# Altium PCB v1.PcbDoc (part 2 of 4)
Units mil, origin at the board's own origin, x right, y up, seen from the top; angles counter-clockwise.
Board outline 4875 x 2022 mil, 4 copper layers (Top Layer, Signal Layer 1, Signal Layer 2, Bottom Layer), stack 64.834 mil thick; 432 components, 288 nets, 1177 pads, 637 vias.
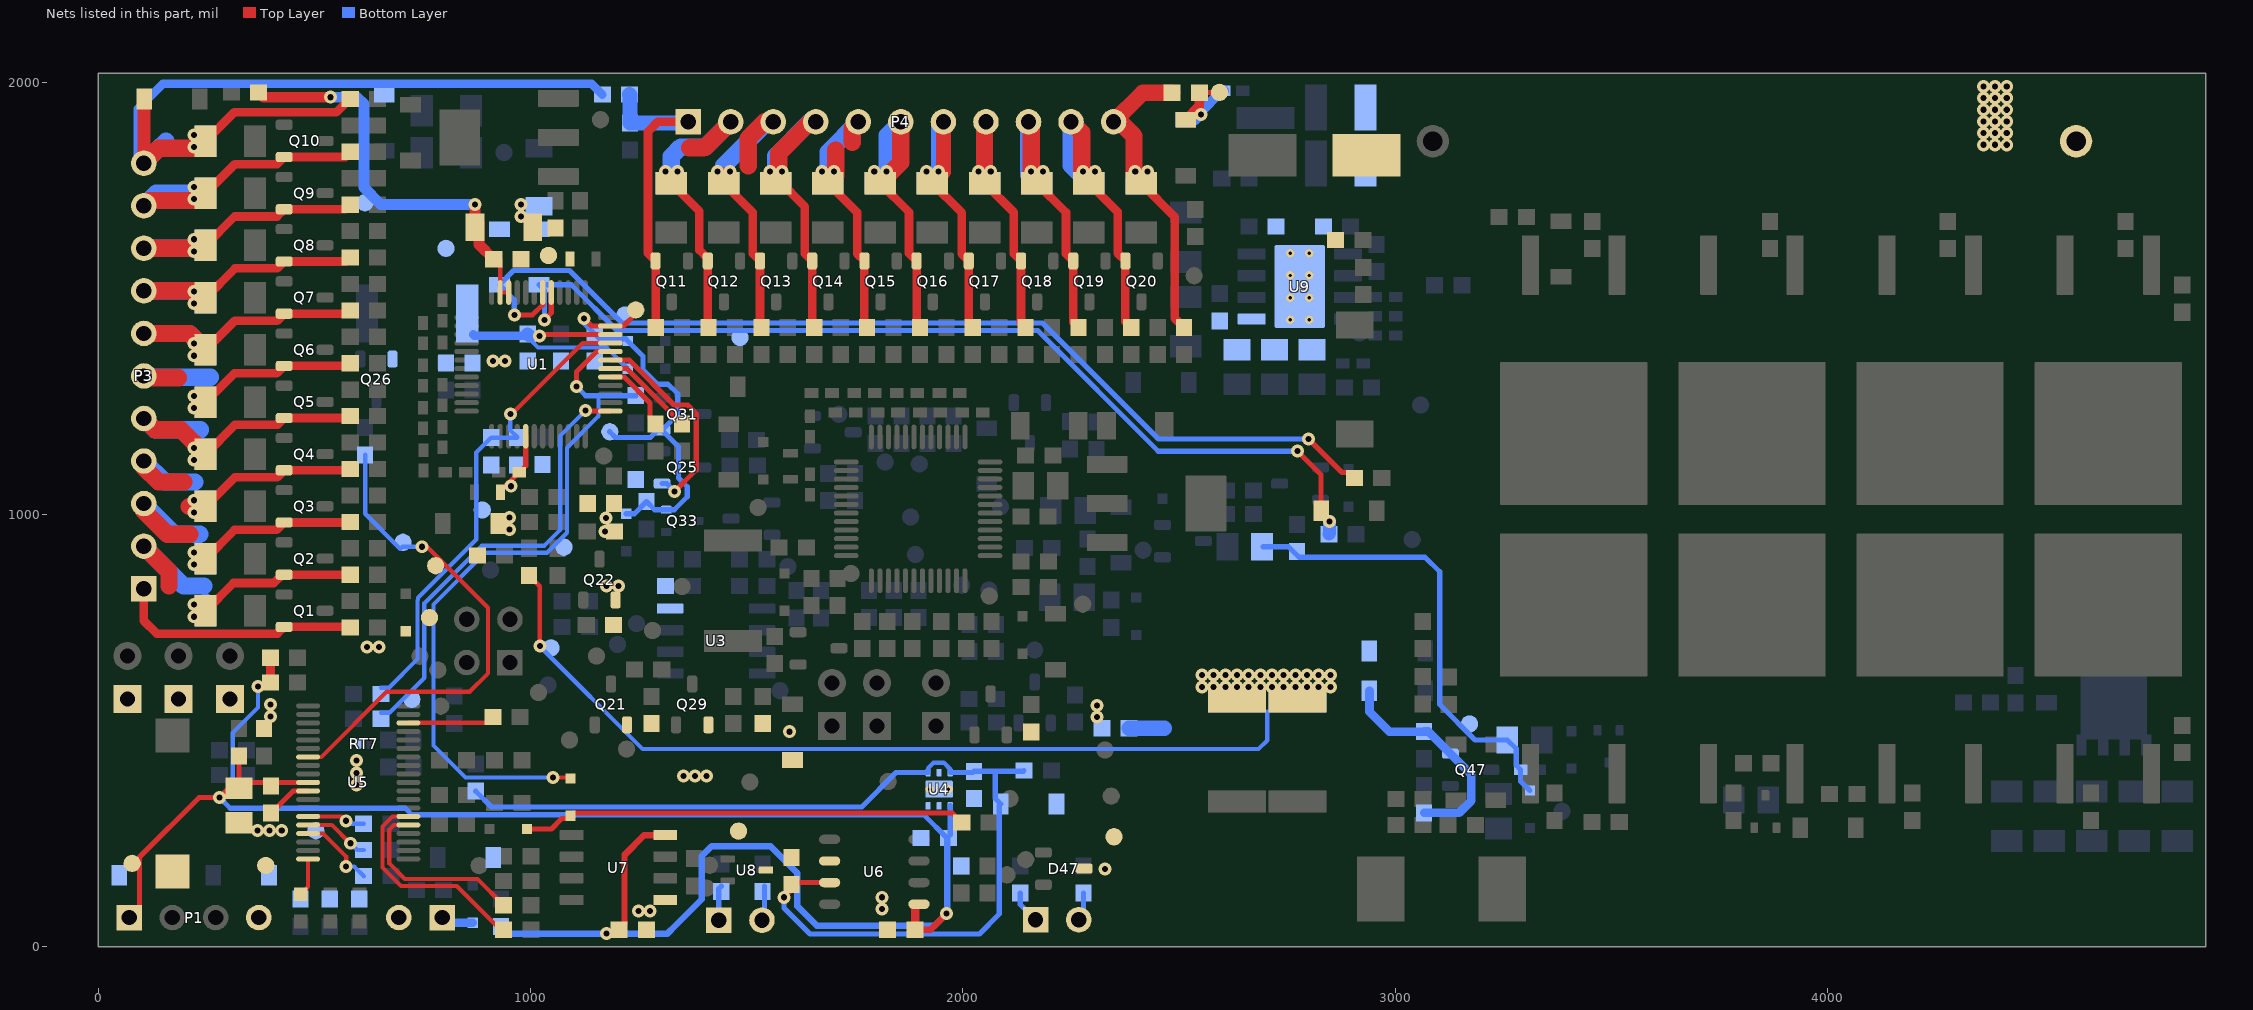
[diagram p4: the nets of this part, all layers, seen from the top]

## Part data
C1 C2 C3 C4 C5 C6 C7 C8 C9 C10 C12 C13 C14 C15 C16 C17 C18 C19 C20 C21: "CAP, CERM, 0.1 µF, 25 V,+/- 10%, X7R, 0402", Cap_Case=0402, Manufacturer=MuRata, Supplier Part Number 1=490-10698-1-ND, TempCo=X7R, Tolerance_%=10, Value2=25V, ValueDisplayed=0.1µF
C11 C22 C36 C37 C42 C43 C46 C64 C66 C68 C69 C70: "CAP, CERM, 0.1 µF, 50 V,+/- 10%, X7R, 0603", Cap_Case=0603, Manufacturer=MuRata, Supplier Part Number 1=490-1519-1-ND, TempCo=X7R, Tolerance_%=10, Value2=50V, ValueDisplayed=0.1µF
C23 C24: library part GRM31CR72A225KA73L, "CAP, CERM, 2.2 µF, 100 V,+/- 10%, X7R, 1206", Cap_Case=1206, Manufacturer="Holy Stone Enterprise", Supplier Part Number 1=490-7209-1-ND, TempCo=X7R, Tolerance_%=10, Value2=100V, ValueDisplayed=2.2µF
C25 C26 C27 C28 C38 C39 C50 C59 C77: "CAP, CERM, 100 pF, 100 V,+/- 5%, C0G/NP0, 0603", Cap_Case=0603, Manufacturer=MuRata, Supplier Part Number 1=490-1351-1-ND, TempCo=C0G/NP0, Tolerance_%=5, Value2=100V, ValueDisplayed=100pF
C29: "CAP, CERM, 2.2 µF, 25 V,+/- 10%, X7R, 0805", Cap_Case=0805, Manufacturer=MuRata, Supplier Part Number 1=490-3331-1-ND, TempCo=X7R, Tolerance_%=10, Value1="0.005 ohm", Value2=25V, ValueDisplayed=2.2µF
C30 C31 C65: "CAP, CERM, 2.2 µF, 16 V,+/- 10%, X7R, 0603", Cap_Case=0603, Manufacturer="Taiyo Yuden", Supplier Part Number 1=587-4864-1-ND, TempCo=X7R, Tolerance_%=10, Value2=16V, ValueDisplayed=2.2µF
C32 C33 C34 C35 C62: "CAP, CERM, 1 µF, 16 V,+/- 10%, X7R, AEC-Q200 Grade 1, 0603", Cap_Case=0603, Manufacturer=MuRata, Supplier Part Number 1=490-5241-6-ND, TempCo=X7R, Tolerance_%=10, Value2=16V, ValueDisplayed=1µF
C40 C41: "CAP, CERM, 0.022 µF, 50 V,+/- 10%, X7R, 0603", Cap_Case=0603, Manufacturer=MuRata, Supplier Part Number 1=490-1517-1-ND, TempCo=X7R, Tolerance_%=10, Value2=50V, ValueDisplayed=0.022µF
C44 C45: "CAP, CERM, 1 µF, 100 V,+/- 10%, X7R, 1206", Cap_Case=1206, Manufacturer=TDK, Supplier Part Number 1=445-4467-1-ND, TempCo=X7R, Tolerance_%=10, Value1="0.004575 ohm", Value2=100V, ValueDisplayed=1µF
C47 C53 C56: "CAP, CERM, 47 pF, 50 V,+/- 5%, C0G/NP0, 0603", Cap_Case=0603, Manufacturer=MuRata, Supplier Part Number 1=490-1419-1-ND, TempCo=C0G/NP0, Tolerance_%=5, Value2=50V, ValueDisplayed=47pF
C48 C49 C51 C52 C54 C55: "CAP, CERM, 470 pF, 50 V,+/- 10%, X7R, 0603", Cap_Case=0603, Manufacturer=MuRata, Supplier Part Number 1=490-1489-1-ND, TempCo=X7R, Tolerance_%=10, Value2=50V, ValueDisplayed=470pF
C57 C58 C60 C61 C73: "CAP, CERM, 0.1 µF, 100 V,+/- 10%, X7R, 0603", Cap_Case=0603, Manufacturer=MuRata, Supplier Part Number 1=490-3285-1-ND, TempCo=X7R, Tolerance_%=10, Value2=100V, ValueDisplayed=0.1µF
C63: "CAP, CERM, 10 µF, 16 V,+/- 10%, X6S, 0805", Cap_Case=0805, Manufacturer=TDK, Supplier Part Number 1=445-14483-1-ND, TempCo=X6S, Tolerance_%=10, Value1="0.002818 ohm", Value2=16V, ValueDisplayed=10µF
C67: "CAP, CERM, 1000 pF, 50 V,+/- 5%, C0G/NP0, 0603", Cap_Case=0603, Manufacturer=MuRata, Supplier Part Number 1=490-1451-1-ND, TempCo=C0G/NP0, Tolerance_%=5, Value2=50V, ValueDisplayed=1000pF
C71 C72: "CAP, CERM, 4.7 µF, 100 V,+/- 10%, X7S, 1210", Cap_Case=1210, Manufacturer=TDK, Supplier Part Number 1=445-8912-1-ND, TempCo=X7S, Tolerance_%=10, Value2=100V, ValueDisplayed=4.7µF
C74: library part UUX2A4R7MCL1GS, "CAP, AL, 10 µF, 100 V, +/- 20%, SMD", Cap_Case=8x6.2mm, Manufacturer=Nichicon, Supplier Part Number 1=493-6282-1-ND, Tolerance_%=20, Value2=100V, ValueDisplayed=10µF
C75: "CAP, CERM, 56 pF, 50 V,+/- 5%, C0G/NP0, 0603", Cap_Case=0603, Manufacturer=MuRata, Supplier Part Number 1=490-1421-1-ND, TempCo=C0G/NP0, Tolerance_%=5, Value2=50V, ValueDisplayed=NC
C76: "CAP, CERM, 2200 pF, 50 V,+/- 10%, X7R, 0402", Cap_Case=0402, Manufacturer=MuRata, Supplier Part Number 1=490-1305-1-ND, TempCo=X7R, Tolerance_%=10, Value2=50V, ValueDisplayed=2200pF
C78: "CAP, CERM, 1500 pF, 50 V,+/- 10%, X7R, 0402", Cap_Case=0402, Manufacturer=MuRata, Supplier Part Number 1=490-3245-1-ND, TempCo=X7R, Tolerance_%=10, Value2=50V, ValueDisplayed=1500pF
C79 C80 C81: "CAP, CERM, 4.7 µF, 16 V,+/- 10%, X7R, 0805", Cap_Case=0805, Manufacturer=MuRata, Supplier Part Number 1=490-4522-1-ND, TempCo=X7R, Tolerance_%=10, Value1="0.006 ohm", Value2=16V, ValueDisplayed=4.7µF
D1 D4 D6 D8 D9 D11 D12 D32 D33 D35 D36: "Diode, Schottky, 100 V, 0.15 A, SOD-123", Manufacturer="Diodes Inc.", Supplier Part Number 1=BAT46W-7FDICT-ND, Value1=0.15A, Value2=0.6V
D2 D5 D10: "Diode, Schottky, 30 V, 0.2 A, SOD-323", Manufacturer="Diodes Inc.", Supplier Part Number 1=BAT42WSDICT-ND, Value1=0.2A, Value2=1V
D3 D7 D15 D39 D40 D41: "Diode, Zener, 3.6 V, 500 mW, SOD-123", Manufacturer="ON Semiconductor", Power_W=0.5, Supplier Part Number 1=MMSZ4685T1GOSCT-ND, Value1=0.5W
D13 D14 D46 D49: "Diode, Schottky, 20 V, 0.5 A, SOD-323F", Manufacturer=Panasonic, Supplier Part Number 1=DB2J20900LCT-ND, Value1=0.5A, Value2=0.5V
D16: library part BAT42WS-7-F, "Diode, Schottky, 30 V, 0.2 A, SOD-323", Manufacturer="Diodes Inc.", Supplier Part Number 1=BAT42WSDICT-ND, Value1=0.2A, Value2=1V
D17 D19 D21 D31 D34: "Diode, Zener, 16 V, 500 mW, SOD-123", Manufacturer="Diodes Inc.", Power_W=0.5, Supplier Part Number 1=MMSZ5246B-FDICT-ND, Value1=0.5W
D18 D20 D26 D27: library part MMSZ5263BT1G, "Diode, Zener, 75V, 500 mW, AEC-Q101, SOD-123", Manufacturer="ON Semiconductor", Power_W=0.5, Supplier Part Number 1=MMSZ5263BT1GOSCT-ND, Value1=0.5W
D22: library part BAT46WJ,115, "Diode, Schottky, 100 V, 0.25 A, SOD-323F", Manufacturer=Nexperia, Supplier Part Number 1=568-6017-1-ND, Value1=0.25A, Value2=0.85V
D23 D24 D25 D28 D38: "Diode, Schottky, 100 V, 0.25 A, SOD-323F", Manufacturer=Nexperia, Supplier Part Number 1=568-6017-1-ND, Value1=0.25A, Value2=0.85V
D29 D48: "Diode, Switching, 100 V, 0.25 A, SOD-523", Manufacturer=Nexperia, Supplier Part Number 1=568-1603-1-ND, Value1=0.25A, Value2=1.25V
D30: "Diode, Zener, 5.1 V, 200 mW, SOD-323", Manufacturer="Diodes Inc.", Power_W=0.2, Supplier Part Number 1=BZT52C5V1S-FDICT-ND, Value1=0.2W
D37: "Diode, Ultrafast, 200 V, 3 A, SMC", Manufacturer=Vishay-Semiconductor, Supplier Part Number 1=ES3D-E3/57TGICT-ND, Value1=3A, Value2=0.9V
D42 D43 D44: "LED, Red, SMD", Color=Red, Manufacturer="Wurth Elektronik", Power_TotalModule=0.072, Supplier Part Number 1=732-4978-1-ND, Value1=0.072W, Value2=2V
D45: "Diode, Zener, 5.6 V, 500 mW, SOD-123", Manufacturer="ON Semiconductor", Power_W=0.5, Supplier Part Number 1=MMSZ4690T1GOSCT-ND, Value1=0.5W
D47: library part NUP2105LT1G, "Diode, TVS, Bi, 24 V, SOT-23", Manufacturer="ON Semiconductor", Power_W=0.35, Supplier Part Number 1=NUP2105LT1GOSCT-ND, Value1=0.35W
F1: library part 0325030, "Fuse, 30 A, 250 VAC, 125 VDC, TH", Alternate Manufacturer=-, Manufacturer=LittleFuse
L1 L2 L3 L4: "Ferrite Bead, 600 ohm @ 100 MHz, 0.2 A, 0603", Manufacturer="Wurth Elektronik", Supplier Part Number 1=732-1583-1-ND, Value1="0.45 ohm", Value2=0.2A, ValueDisplayed="600 ohm"
L5: "Inductor, Shielded, 1 µH, 2.7 A, 0.039 ohm, SMD", Manufacturer="Wurth Elektronik", Supplier Part Number 1=732-4863-1-ND, Value1="0.039 ohm", Value2=2.7A, ValueDisplayed=10µH
L6: "Inductor, Shielded Drum Core, Metal Composite, 68 µH, 0.87 A, 0.239 ohm, SMD", Manufacturer="Wurth Elektronik", Supplier Part Number 1=732-1201-1-ND, Value1="0.239 ohm", Value2=0.87A, ValueDisplayed=68µH
P1: "Header, 4-Pin"
P2: "Header, 2-Pin, Dual row"
P3 P4: "Header, 11-Pin"
P5 P6 P7: "Header, 2-Pin"
Q1 Q2 Q3 Q4 Q5 Q6 Q7 Q8 Q9 Q10 Q11 Q12 Q13 Q14 Q15 Q16 Q17 Q18 Q19 Q20: library part "BSR14, Nexperia", "Transistor, NPN, 40 V, 0.8 A, SOT-23", Manufacturer=Nexperia, Supplier Part Number 1=568-6225-1-ND, Value1="0.8 A", Value2=300
Q21: library part "BC846B,215, Nexperia", "Transistor, NPN, 65 V, 0.1 A, SOT-23", Manufacturer=Nexperia, Supplier Part Number 1=568-1632-1-ND, Value1="0.1 A", Value2=450
Q22 Q25 Q26 Q29 Q31 Q32: library part "MMBTA05LT1G, ON Semiconductor", "Transistor, NPN, 60 V, 0.5 A, AEC-Q101, SOT-23", Manufacturer="ON Semiconductor", Supplier Part Number 1=MMBTA05LT1GOSCT-ND, Value1="0.5 A"
Q23 Q24: library part "FZT493TA, Diodes Inc.", "Transistor, NPN, 60 V, 1 A, SOT-223", Manufacturer="Diodes Inc.", Supplier Part Number 1=FZT493CT-ND, Value1="1 A", Value2=300
Q27 Q28 Q30 Q34 Q35: library part "MMBTA56LT1G, ON Semiconductor", "Transistor, PNP, 80 V, 0.5 A, SOT-23", Manufacturer="ON Semiconductor", Supplier Part Number 1=MMBTA56LT1GOSDKR-ND, Value1="0.5 A"
Q33 Q49: "MOSFET, P-CH, -20 V, -0.82 A, SOT-323", Alternate Manufacturer=None, Manufacturer="Diodes Inc.", Supplier Part Number 1=DMG1013UW-7DICT-ND, Value1="0.75 ohm", Value2="0.622 nC"
Q36 Q37 Q38 Q39 Q42 Q43 Q44 Q45: "MOSFET, N-CH, 100 V, 200 A, KTT0002A (TO-263-2)", Alternate Manufacturer=None, Manufacturer="Texas Instruments", Supplier Part Number 1=296-41136-1-ND, Value1="? ohm", Value2="118 nC"
Q40: "MOSFET, P-CH, -150 V, -3 A, PowerPAK SO-8", Alternate Manufacturer=None, Manufacturer=Vishay-Siliconix, Supplier Part Number 1=SI7439DP-T1-E3CT-ND, Value1="? ohm", Value2="88 nC"
Q41: "MOSFET, P-CH, -150 V, -0.53 A, SOT-23", Alternate Manufacturer=None, Manufacturer=Vishay-Siliconix, Supplier Part Number 1=SI2325DS-T1-E3CT-ND, Value1="? ohm", Value2="7.7 nC"
Q46: library part "FMMT495TA, Diodes Inc.", "Transistor, NPN, 150 V, 1 A, AEC-Q101, SOT-23", Manufacturer="Diodes Inc.", Supplier Part Number 1=FMMT495CT-ND, Value1="1 A", Value2=300
Q47: library part BSS123, "MOSFET, N-CH, 250V, 0.35 A, SOT-23", Alternate Manufacturer=None, Manufacturer="Fairchild Semiconductor", Supplier Part Number 1=BSS123NCT-ND, Value1="10 ohm", Value2="1.8 nC"
Q48: "MOSFET, N-CH, 60 V, 0.115 A, SOT-323", Alternate Manufacturer=None, Manufacturer="Diodes Inc.", Supplier Part Number 1=2N7002W-FDICT-ND, Value1="7.5 ohm", Value2="? nC"
R1 R3 R5 R7 R9 R11 R13 R15 R17 R19 R43 R44 R46 R48 R50 R52 R54 R56 R58 R60: "RES, 80.6, 1%, 0.25 W, 1206", Manufacturer=Vishay-Dale, Power_W=0.25, Supplier Part Number 1=541-80.6FCT-ND, TempCo="100 ppm/C", Tolerance_%=1, Value1=1%, Value2=0.25W, Value_Code=80R6
R2 R4 R6 R8 R10 R12 R14 R16 R18 R20 R42 R45 R47 R49 R51 R53 R55 R57 R59 R61: "RES, 80.6, 1%, 0.25 W, 1206", Manufacturer=Vishay-Dale, Power_W=0.25, Supplier Part Number 1=541-80.6FCT-ND, TempCo="100 ppm/C", Tolerance_%=1, Value1=1%, Value2=0.25W, Value_Code=80R6, ValueDisplayed=80.6
R21 R23 R25 R27 R29 R31 R33 R35 R37 R39 R64 R66 R68 R70 R72 R74 R76 R78 R80 R82 R88 R90 R97 R98 R102 R103 R105 R106 R180 R181 R182 R183 R184 R185 R186 R187 R188 R192 R193 R194 R195 R196 R197 R201 R202 R209: "RES, 100, 1%, 0.1 W, 0603", Manufacturer=Vishay-Dale, Power_W=0.1, Supplier Part Number 1=541-100HCT-ND, TempCo="100 ppm/C", Tolerance_%=1, Value1=1%, Value2=0.1W, Value_Code=100R, ValueDisplayed=100
R22 R24 R26 R28 R30 R32 R34 R36 R38 R40 R65 R67 R69 R71 R73 R75 R77 R79 R81 R83: "RES, 300, 5%, 0.1 W, 0603", Manufacturer=Vishay-Dale, Power_W=0.1, Supplier Part Number 1=541-300GCT-ND, TempCo="200 ppm/C", Tolerance_%=5, Value1=5%, Value2=0.1W, Value_Code=300R, ValueDisplayed=300
R41 R84: "RES, 20.0, 1%, 0.1 W, 0603", Manufacturer=Vishay-Dale, Power_W=0.1, Supplier Part Number 1=541-20.0HCT-ND, TempCo="100 ppm/C", Tolerance_%=1, Value1=1%, Value2=0.1W, Value_Code=20R0, ValueDisplayed=20.0
R62 R63 R120 R216 R217: "RES, 0, 5%, 0.1 W, 0603", Manufacturer=Vishay-Dale, Power_W=0.1, Supplier Part Number 1=541-0.0GCT-ND, TempCo="200 ppm/C", Tolerance_%=5, Value1=5%, Value2=0.1W, Value_Code=0000, ValueDisplayed=0
R85 R87 R94 R95 R96 R110 R173 R179 R203 R204 R207: "RES, 10.0 k, 1%, 0.1 W, 0603", Manufacturer=Vishay-Dale, Power_W=0.1, Supplier Part Number 1=541-10.0KHCT-ND, TempCo="100 ppm/C", Tolerance_%=1, Value1=1%, Value2=0.1W, Value_Code=10k0, ValueDisplayed=10.0k
R86 R91 R100 R101 R140 R148 R165 R167 R174: "RES, 10 M, 5%, 0.1 W, 0603", Manufacturer=Vishay-Dale, Power_W=0.1, Supplier Part Number 1=541-10MGCT-ND, TempCo="200 ppm/C", Tolerance_%=5, Value1=5%, Value2=0.1W, Value_Code=10M0, ValueDisplayed=10M
R89: "RES, 2.00 M, 1%, 0.1 W, 0603", Manufacturer="Yageo America", Power_W=0.1, Supplier Part Number 1=311-2.00MHRCT-ND, TempCo="200 ppm/C", Tolerance_%=1, Value1=1%, Value2=0.1W, Value_Code=2M00, ValueDisplayed=2.00M
R92 R93: "RES, 499 k, 1%, 0.1 W, 0603", Manufacturer=Vishay-Dale, Power_W=0.1, Supplier Part Number 1=541-499KHCT-ND, TempCo="100 ppm/C", Tolerance_%=1, Value1=1%, Value2=0.1W, Value_Code=499k
R99 R104 R199 R200: "RES, 4.70 k, 1%, 0.1 W, 0603", Manufacturer="Yageo America", Power_W=0.1, Supplier Part Number 1=311-4.70KHRCT-ND, TempCo="200 ppm/C", Tolerance_%=1, Value1=1%, Value2=0.1W, Value_Code=4k70, ValueDisplayed=4.70k
R107 R111: library part CRCW1206619RFKEA, "RES, 619, 1%, 0.25 W, 1206", Manufacturer=Yageo, Power_W=0.25, Supplier Part Number 1=541-619FCT-ND, TempCo="100 ppm/C", Tolerance_%=1, Value1=1%, Value2=0.25W, Value_Code=619R, ValueDisplayed=619
R108 R109: library part CRCW1206154RFKEA, "RES, 154, 1%, 0.25 W, 1206", Manufacturer=Yageo, Power_W=0.25, Supplier Part Number 1=541-154FCT-ND, TempCo="100 ppm/C", Tolerance_%=1, Value1=1%, Value2=0.25W, Value_Code=154R, ValueDisplayed=154
R112 R118: library part CRCW2512200RJNEG, "RES, 200, 5%, 1 W, AEC-Q200 Grade 0, 2512", Manufacturer=Yageo, Power_W=1, Supplier Part Number 1=541-200XCT-ND, TempCo="200 ppm/C", Tolerance_%=5, Value1=5%, Value2=1W, Value_Code=200R, ValueDisplayed=200
R113: "RES, 2.00 k, 1%, 0.1 W, 0603", Manufacturer="Yageo America", Power_W=0.1, Supplier Part Number 1=311-2.00KHRCT-ND, TempCo="200 ppm/C", Tolerance_%=1, Value1=1%, Value2=0.1W, Value_Code=2k00, ValueDisplayed=2.00k
R114 R128 R132 R136 R138: "RES, 150 k, 1%, 0.1 W, 0603", Manufacturer=Vishay-Dale, Power_W=0.1, Supplier Part Number 1=541-150KHCT-ND, TempCo="100 ppm/C", Tolerance_%=1, Value1=1%, Value2=0.1W, Value_Code=150k
R115 R119 R122 R124 R127 R129 R133 R215: "RES, 200 k, 1%, 0.1 W, 0603", Manufacturer=Vishay-Dale, Power_W=0.1, Supplier Part Number 1=541-200KHCT-ND, TempCo="100 ppm/C", Tolerance_%=1, Value1=1%, Value2=0.1W, Value_Code=200k
R116 R130 R134: "RES, 80.6 k, 1%, 0.1 W, 0603", Manufacturer=Vishay-Dale, Power_W=0.1, Supplier Part Number 1=541-80.6KHCT-ND, TempCo="100 ppm/C", Tolerance_%=1, Value1=1%, Value2=0.1W, Value_Code=80k6, ValueDisplayed=80.6k
R117 R131 R135: "RES, 300, 1%, 0.1 W, 0603", Manufacturer="Yageo America", Power_W=0.1, Supplier Part Number 1=311-300HRCT-ND, TempCo="200 ppm/C", Tolerance_%=1, Value1=1%, Value2=0.1W, Value_Code=300R, ValueDisplayed=300
R121: "RES, 330 k, 5%, 0.1 W, 0603", Manufacturer=Vishay-Dale, Power_W=0.1, Supplier Part Number 1=541-330KGCT-ND, TempCo="200 ppm/C", Tolerance_%=5, Value1=5%, Value2=0.1W, Value_Code=330k
R123: "RES, 33.0 k, 1%, 0.1 W, 0603", Manufacturer="Yageo America", Power_W=0.1, Supplier Part Number 1=311-33.0KHRCT-ND, TempCo="200 ppm/C", Tolerance_%=1, Value1=1%, Value2=0.1W, Value_Code=33k0, ValueDisplayed=33.0k
R125: "RES, 26.1 k, 1%, 0.1 W, 0603", Manufacturer=Vishay-Dale, Power_W=0.1, Supplier Part Number 1=541-26.1KHCT-ND, TempCo="100 ppm/C", Tolerance_%=1, Value1=1%, Value2=0.1W, Value_Code=26k1, ValueDisplayed=26.1k
R126 R137 R218: "RES, 10.0, 1%, 0.1 W, 0603", Manufacturer="Yageo America", Power_W=0.1, Supplier Part Number 1=311-10.0HRCT-ND, TempCo="200 ppm/C", Tolerance_%=1, Value1=1%, Value2=0.1W, Value_Code=10R0, ValueDisplayed=10.0
R139 R189 R190 R191: "RES, 499, 1%, 0.1 W, 0603", Manufacturer="Yageo America", Power_W=0.1, Supplier Part Number 1=311-499HRCT-ND, TempCo="200 ppm/C", Tolerance_%=1, Value1=1%, Value2=0.1W, Value_Code=499R, ValueDisplayed=499
R141 R142 R143 R144 R158 R159 R160 R161: "RES, 75.0, 1%, 0.1 W, 0603", Manufacturer=Vishay-Dale, Power_W=0.1, Supplier Part Number 1=541-75.0HCT-ND, TempCo="100 ppm/C", Tolerance_%=1, Value1=1%, Value2=0.1W, Value_Code=75R0, ValueDisplayed=75.0
R145: "RES, 49.9 k, 0.1%, 0.1 W, 0603", Manufacturer="Yageo America", Power_W=0.1, TempCo="25 ppm/C", Value1=0.1%, Value2=0.1W, Value_Code=49k9, ValueDisplayed=49.9k
R146: "RES, 1.0 M, 5%, 0.1 W, 0603", Manufacturer=Vishay-Dale, Power_W=0.1, Supplier Part Number 1=541-1.0MGCT-ND, TempCo="200 ppm/C", Tolerance_%=5, Value1=5%, Value2=0.1W, Value_Code=1M00, ValueDisplayed=1.0M
R147: "RES, 10.0, 1%, 0.125 W, 0805", Manufacturer=Vishay-Dale, Power_W=0.125, Supplier Part Number 1=541-10.0CCT-ND, TempCo="100 ppm/C", Tolerance_%=1, Value1=1%, Value2=0.125W, Value_Code=10R0, ValueDisplayed=10.0
R149: library part CRCW0603390RFKEA, "RES, 390, 1%, 0.1 W, 0603", Manufacturer=Vishay-Dale, Power_W=0.1, Supplier Part Number 1=541-390HCT-ND, TempCo="100 ppm/C", Tolerance_%=1, Value1=1%, Value2=0.1W, Value_Code=390R
R150 R151 R152 R153 R154: library part CRCW1206511RFKEA, "RES, 511, 1%, 0.25 W, 1206", Manufacturer=Yageo, Power_W=0.25, Supplier Part Number 1=541-511FCT-ND, TempCo="100 ppm/C", Tolerance_%=1, Value1=1%, Value2=0.25W, Value_Code=511R, ValueDisplayed=511
R155 R166: library part CRCW080556K0JNEA, "RES, 56 k, 5%, 0.125 W, 0805", Manufacturer=Yageo, Power_W=0.125, Supplier Part Number 1=541-56KACT-ND, TempCo="200 ppm/C", Tolerance_%=5, Value1=5%, Value2=0.125W, Value_Code=56k0, ValueDisplayed=56k
R156: library part CRCW0603806RFKEA, "RES, 806, 1%, 0.1 W, 0603", Manufacturer=Vishay-Dale, Power_W=0.1, Supplier Part Number 1=541-806HCT-ND, TempCo="100 ppm/C", Tolerance_%=1, Value1=1%, Value2=0.1W, Value_Code=806R
R157: library part CRCW0805806RFKEA, "RES, 806, 1%, 0.125 W, 0805", Manufacturer=Yageo, Power_W=0.125, Supplier Part Number 1=541-806CCT-ND, TempCo="100 ppm/C", Tolerance_%=1, Value1=1%, Value2=0.125W, Value_Code=806R, ValueDisplayed=806
R162: "RES, 47.0, 1%, 0.1 W, 0603", Manufacturer="Yageo America", Power_W=0.1, Supplier Part Number 1=311-47.0HRCT-ND, TempCo="200 ppm/C", Tolerance_%=1, Value1=1%, Value2=0.1W, Value_Code=47R0, ValueDisplayed=47.0
R163: library part CRCW060310M0JNEA, "RES, 10 M, 5%, 0.1 W, 0603", Manufacturer=Vishay-Dale, Power_W=0.1, Supplier Part Number 1=541-10MGCT-ND, TempCo="200 ppm/C", Tolerance_%=5, Value1=5%, Value2=0.1W, Value_Code=10M0
R164: "RES, 0, 5%, 0.1 W, 0603", Manufacturer=Vishay-Dale, Power_W=0.1, Supplier Part Number 1=541-0.0GCT-ND, TempCo="200 ppm/C", Tolerance_%=5, Value1=5%, Value2=0.1W, Value_Code=0000, ValueDisplayed=NC
R168: "RES, 100, 1%, 0.125 W, 0805", Manufacturer=Vishay-Dale, Power_W=0.125, Supplier Part Number 1=541-100CCT-ND, TempCo="100 ppm/C", Tolerance_%=1, Value1=1%, Value2=0.125W, Value_Code=100R, ValueDisplayed=100
R169: "RES, 620 k, 1%, 0.1 W, 0603", Manufacturer="Yageo America", Power_W=0.1, Supplier Part Number 1=311-620KHRCT-ND, TempCo="200 ppm/C", Tolerance_%=1, Value1=1%, Value2=0.1W, Value_Code=620k
R170 R172 R176: "RES, 5.1 k, 5%, 0.1 W, 0603", Manufacturer=Vishay-Dale, Power_W=0.1, Supplier Part Number 1=541-5.1KGCT-ND, TempCo="200 ppm/C", Tolerance_%=5, Value1=5%, Value2=0.1W, Value_Code=5k10, ValueDisplayed=5.1k
R171: library part CRCW08051K50JNEA, "RES, 1.5 k, 5%, 0.125 W, 0805", Manufacturer=Yageo, Power_W=0.125, Supplier Part Number 1=541-1.5KACT-ND, TempCo="200 ppm/C", Tolerance_%=5, Value1=5%, Value2=0.125W, Value_Code=1k50, ValueDisplayed=1.5k
R175: "RES, 806, 1%, 0.1 W, 0603", Manufacturer=Vishay-Dale, Power_W=0.1, Supplier Part Number 1=541-806HCT-ND, TempCo="100 ppm/C", Tolerance_%=1, Value1=1%, Value2=0.1W, Value_Code=806R, ValueDisplayed=806
R177: "RES, 604 k, 1%, 0.1 W, 0603", Manufacturer="Yageo America", Power_W=0.1, Supplier Part Number 1=311-604KHRCT-ND, TempCo="200 ppm/C", Tolerance_%=1, Value1=1%, Value2=0.1W, Value_Code=604k
R178: "RES, 68.0 k, 1%, 0.1 W, 0603", Manufacturer="Yageo America", Power_W=0.1, Supplier Part Number 1=311-68.0KHRCT-ND, TempCo="200 ppm/C", Tolerance_%=1, Value1=1%, Value2=0.1W, Value_Code=68k0, ValueDisplayed=68.0k
R198: "RES, 47.0 k, 1%, 0.1 W, 0603", Manufacturer="Yageo America", Power_W=0.1, Supplier Part Number 1=311-47.0KHRCT-ND, TempCo="200 ppm/C", Tolerance_%=1, Value1=1%, Value2=0.1W, Value_Code=47k0, ValueDisplayed=47.0k
R205 R206: "RES, 60.4, 1%, 0.1 W, 0603", Manufacturer="Yageo America", Power_W=0.1, Supplier Part Number 1=311-60.4HRCT-ND, TempCo="200 ppm/C", Tolerance_%=1, Value1=1%, Value2=0.1W, Value_Code=60R4, ValueDisplayed=60.4
R208: "RES, 120, 1%, 0.1 W, 0603", Manufacturer="Yageo America", Power_W=0.1, Supplier Part Number 1=311-120HRCT-ND, TempCo="200 ppm/C", Tolerance_%=1, Value1=1%, Value2=0.1W, Value_Code=120R, ValueDisplayed=120
R210: "RES, 82.5 k, 1%, 0.1 W, 0603", Manufacturer=Vishay-Dale, Power_W=0.1, Supplier Part Number 1=541-82.5KHCT-ND, TempCo="100 ppm/C", Tolerance_%=1, Value1=1%, Value2=0.1W, Value_Code=82k5, ValueDisplayed=82.5k
R211: "RES, 0, 5%, 0.063 W, 0402", Manufacturer=Vishay-Dale, Power_W=0.063, Supplier Part Number 1=541-0.0JCT-ND, TempCo="200 ppm/C", Tolerance_%=5, Value1=5%, Value2=0.063W, Value_Code=0000, ValueDisplayed=0
R212: "RES, 499 k, 1%, 0.1 W, 0603", Manufacturer="Yageo America", Power_W=0.1, Supplier Part Number 1=311-499KHRCT-ND, TempCo="200 ppm/C", Tolerance_%=1, Value1=1%, Value2=0.1W, Value_Code=499k, ValueDisplayed=NC
R213: library part CRCW0402523KFKED, "RES, 523 k, 1%, 0.063 W, 0402", Manufacturer=Yageo, Power_W=0.063, Supplier Part Number 1=541-523KLCT-ND, TempCo="100 ppm/C", Tolerance_%=1, Value1=1%, Value2=0.063W, Value_Code=523k
R214: "RES, 63.4 k, 1%, 0.1 W, 0603", Manufacturer=Vishay-Dale, Power_W=0.1, Supplier Part Number 1=541-63.4KHCT-ND, TempCo="100 ppm/C", Tolerance_%=1, Value1=1%, Value2=0.1W, Value_Code=63k4, ValueDisplayed=63.4k
R219 R220 R221 R222: "RES, 0.002, 1%, 2 W, 2512", Manufacturer="Stackpole Electronics Inc", Power_W=2, Supplier Part Number 1=CSNL2512FT2L00CT-ND, TempCo="50 ppm/C", Tolerance_%=1, Value1=1%, Value2=2W, Value_Code=2L000, ValueDisplayed=0.002
RT1 RT2 RT3 RT4 RT5 RT6: library part 103AT-2, "THERMISTOR NTC 10KOHM BEAD", Manufacturer=Cantherm, Power_W=0.01, Tolerance_%=1
RT7: library part CMP-0084566-1, "Thermistor, DEC0002A (X1SON-2)", Alternate Manufacturer="Texas Instruments", Alternate PartNumber=TMP6131DECT
S1: "Switch, Tactile, SPST-NO, 0.05A, 12V, SMD", CurrentRating_mA=50, Manufacturer="C&K Components", Supplier Part Number 1=CKN10388CT-ND
U1 U2: library part CMP-0750064-1, "Multicell Battery Monitor and Protection Family, PFB0048A (TQFP-48)", Alternate Manufacturer="Texas Instruments", Alternate PartNumber=BQ76942PFBT
U3: library part CMP-0091761-1, "I²C Digital Isolator 3000Vrms 2 Channel  50kV/µs CMTI 8-SOIC (0.154\", 3.90mm Width)", Digikey Part Number=296-ISO1640BDRCT-ND, Manufacturer="Texas Instruments", Max Supply Voltage=5.5V, Min Supply Voltage=2.25V, Mouser Part Number=595-ISO1640BDR, Nominal Supply Current=2.7-5.3mA, Operating Temperature Range="-40°C to +125°C"
U4: library part CMP-0078340-1, "300-mA, 18-V, Low IQ, Low Dropout Voltage Regulator with Power Good, DRV0006A (WSON-6)", Alternate Manufacturer="Texas Instruments", PartNumber=TPS7A2533DRVR
U5: library part CMP-0084060-1, "24MHz 105C ULP Microcontroller With 32 KB FRAM, 4 KB SRAM, 44 IO, 12-bit ADC, DBT0038A (TSSOP-38)", Alternate Manufacturer="Texas Instruments", Alternate PartNumber=MSP430FR2155TDBT, Operating Temperature Range="-40 to 105 C", Rating=Catalog
U6: library part CMP-0075993-1, "Automotive Fault Protected CAN Transceiver With Flexible Data-Rate, D0008A (SOIC-8)", Alternate Manufacturer="Texas Instruments", Alternate PartNumber=TCAN1042HVDQ1
U7: library part CMP-0089978-1, "500 kbps RS-485 Transceivers With ±8-kV IEC ESD Protection", Manufacturer="Texas Instruments", Max Supply Voltage=5.5V, Min Supply Voltage=4.5V, Nominal Supply Current=275-440uA, Operating Temperature Range="-40°C to +125°C", PartNumber=THVD2410DR
U8: "ESD Protection Array for AC Signal Data Interface, 2 Channels, -40 to +85 degC, 3-pin SC70 (DCK), Green (RoHS & no Sb/Br)", Alternate Manufacturer="Texas Instruments", Alternate PartNumber=Equivalent, Breakdown Voltage(Min)(V)=+/-14, IO Capacitance(Typ)(pF)=15, IO Leakage Current(nA)=50, Supplier Part Number 1=296-25281-2-ND
U9: library part CMP-0861029-1, "0.3-A,120-V, Step-Down Converter with Fly-buck Capability", Alternate Manufacturer="Texas Instruments"

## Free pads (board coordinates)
  round 40 smd: 1(78,193.41) 1(387,188.5) 1(743.53,672.61) 1(766,762) 1(780,882.18) 1(785,641) 1(792,557) 1(880.69,188.19) 1(1018,588.55) 1(1041,1600) 1(1090,479.09) 1(1152.06,673) 1(1161.55,1914) 1(1169,1136) 1(1222,457.69) 1(1243,1474) 1(1282,732) 1(1349.81,833.77) 1(1406.7,136.1) 1(1414,189.11) 1(1481,268) 1(1507,381.55) 1(1526.16,1017) 1(1741,864.03) 1(1827,382.66) 1(2061,812) 1(2102,167) 1(2109,343) 1(2145.3,202) 1(2277.23,793) 1(2328.86,455.7) 1(2343,349) 1(2349.57,255) 1(2535,1553) 1(2593.45,1977.23)
  round 40 smd far side: 1(503,269) 1(616.67,1721.88) 1(704.74,936.29) 1(725,573) 1(804,1616.4) 1(888,1011) 1(907,872) 1(938,1838) 1(1040,606) 1(1047,692) 1(1077,924.98) 1(1183,1192) 1(1201,700) 1(1218,1462) 1(1245,748) 1(1484.36,1410) 1(1577,592.88) 1(1595,880) 1(1713,1232.51) 1(1820,1121.9) 1(1879,995) 1(1890,908) 1(1899,1117.5) 1(1997,837) 1(2060,826) 1(2087,1018.54) 1(2166,687) 1(2417,918) 1(2917.33,1421) 1(3039.46,942.63) 1(3059,1254) 1(3171.85,516.04) 1(3386,314)

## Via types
v1: diameter 30, hole 14, Top Layer to Bottom Layer, 615 vias
v2: diameter 19.68, hole 7.87, Top Layer to Bottom Layer, 18 vias
v3: diameter 19.68, hole 7.87, Top Layer to Bottom Layer, tented both sides, 4 vias

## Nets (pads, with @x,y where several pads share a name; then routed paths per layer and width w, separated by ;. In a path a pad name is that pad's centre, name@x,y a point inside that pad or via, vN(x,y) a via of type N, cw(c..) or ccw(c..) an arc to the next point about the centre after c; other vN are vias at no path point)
3V3: C63.2 C64.2 C65.1 C68.1 C69.1 P1.1 pad.1@78,193.41 R178.2 R198.2 R199.2 R200.2 U4.1 U5.10 U6.5 U7.8 | length 4737.9
  Top Layer w12: P1.1@71,68 95,92 95,208 233,346 v1(280,346) 301,367 C63.2@325,367 C63.2@325,370.65 ; R198.2@325,442.36 C63.2@325,370.65 ; U5.10@484.86,380.65 335,380.65 C63.2@325,370.65
  Top Layer w15: C69.1@1204.5,39.93 1217,52.43 1217,213.02 1262.82,258.84 U7.8@1296.06,258.84 ; C68.1@1888.99,40 1925,40 v1(1962,77)
  Top Layer w20: R200.2@398.01,612 R199.2@398.01,669 ; C68.1@1888.99,40 1890.02,41.03 U6.5@1890.02,99
  Bottom Layer w10: v1(280,346) 281.45,346 311,375.55 311,496 369,554 v1(369,603)
  Bottom Layer w12: v1(280,346) 305,321 710,321 725,306 1909.43,306 C65.1@1963.43,252 ; C65.1@1970.59,259.16 U4.1@1970.59,326.61
  Bottom Layer w15: R178.2@931,47.5 933.5,50 952.5,31 v1(1175,31) 1316.5,31 1335.5,50 1396,110.5 1396,210.48 1418.52,233 1554.84,233 1617,170.84 1617,94 1661.5,49.5 1934.5,49.5 v1(1962,77) ; v1@1963.43,79.43 C65.1@1963.43,252
5V: C62.1 C66.1 D45.1 R120.2 R216.2 U4.4 U4.6 U6.3 | length 2387.2
  Top Layer w12: v1(1586,115) 1603,132 C66.1@1603,144.5 1607.5,149 U6.3@1699.98,149
  Bottom Layer w10: U4.4@1919.41,403.39 1919.41,413.41 1932,426 1956,426 1970.59,411.41 U4.6@1970.59,403.39
  Bottom Layer w12: R120.2@873,360.5 909.5,324 1766,324 1845.39,403.39 U4.4@1919.41,403.39 ; v1(1586,115) 1586,90 1646,30 2038,30 2084.2,76.2 2084.2,327.64 D45.1@2087.56,331 2075,343.56 2075,406.5 ; U4.6@1970.59,403.39 2022.89,403.39 C62.1@2026,406.5 2075,406.5 ; R216.2@2141.5,408 2140,406.5 2075,406.5
485_RX_EN: R204.1 U5.25 | length 504.6
  Top Layer w10: U5.25@717.14,301.91 680.28,301.91 657,278.63 657,184 699.81,141.19 828.81,141.19 930,40 R204.1@937.5,40
485_TX_EN: R203.1 U5.24 | length 431.8
  Top Layer w10: U5.24@717.14,282.22 683.22,282.22 673,272 673,192.96 708.77,157.19 876.91,157.19 R203.1@937.5,96.6
485A: L3.1 P6.1 | length 81
  Bottom Layer w12: P6.1@1435,62 1435,134.5 L3.1@1441,140.5
485B: L4.1 P6.2 | length 81
  Bottom Layer w12: P6.2@1535,62 1541,68 L4.1@1541,140.5
BAT+: F1.2
  other v1: 4361,1856 4388,1856 4415,1856 4361,1883 4388,1883 4415,1883 4361,1910 4388,1910 4415,1910 4361,1937 4388,1937 4415,1937 4361,1964 4388,1964 4415,1964 4361,1991 4388,1991 4415,1991
BAT_IN: D9.2 D12.2 D48.2 pad.1@2593.45,1977.23 R218.1 | length 218.7
  Top Layer w12: R218.1@2546.83,1976.52 2547.54,1977.23 pad.1@2593.45,1977.23
  Top Layer w23: D9.2@2515.33,1913.47 2546.83,1944.96 R218.1@2546.83,1976.52
  Bottom Layer w23: D12.2@2537.8,1913.47 v1(2550.33,1926) ; v1@2547.33,1929 2599.56,1981.22 D48.2@2603.68,1981.22
BOT_ALERT: pad.1@725,573 R182.2 U1.25 | length 1048.9
  Top Layer w12: v1(1127,1241) 1128.27,1239.73 U1.25@1184.34,1239.73
  Bottom Layer w10: R182.2@653.5,542 673,542 754,623 754,795.19 886.81,928 1031,928 1068,965 1068,1182 v1(1127,1241)
BOT_BAT: C23.2 C25.2 pad.1@616.67,1721.88 R88.2 U1.46 U1.47 | length 944.3
  Top Layer w10: C25.2@929.42,1589.91 U1.47@929.42,1514.34 U1.46@949.1,1514.34
  Top Layer w25: R88.2@370.5,1977 381.5,1966 v1(537,1966) ; C23.2@871,1689.14 v1(871,1718) ; C23.2@880.07,1676.07 880.07,1625.43 C25.2@914.5,1591
  Bottom Layer w25: v1(537,1966) 598,1966 614,1950 614,1757 653,1718 v1(871,1718)
BOT_CB: pad.1@704.74,936.29 pad.1@780,882.18 R113.1 U5.7 | length 1162.5
  Top Layer w10: U5.7@484.86,439.7 515.7,439.7 666.87,590.87 858.87,590.87 901,633 901,785 760,926 v1(749,926)
  Bottom Layer w10: R113.1@617,1138.5 617,1002.4 698.4,921 703.4,926 v1(749,926)
BOT_DDSG: D46.1 D49.1 R162.1 | length 1030.4
  Top Layer w12: D46.1@991.31,273 1048,273 1072,297 1082,297 1088.39,303.39 D49.1@1092,303.39 1098.61,310 1975.29,310 R162.1@1997.29,288
BOT_LD: D26.1 D32.2 pad.1@1484.36,1410 R169.1 U1.41 | length 2260.9
  Top Layer w12: v1(1032,1451) 1047.53,1466.53 U1.41@1047.53,1514.34 ; v1(2773.8,1147.12) 2828.53,1092.39 D32.2@2828.53,1009
  Bottom Layer w12: v1(1032,1451) 1032,1519.05 D26.1@1019,1532.05 1093.95,1532.05 1200,1426 2173,1426 2451.88,1147.12 v1(2773.8,1147.12)
  Bottom Layer w30: R169.1@2846.5,955 2848,956.5 v1(2848,984)
BOT_PACK: D27.1 pad.1@1218,1462 R170.1 U1.42 | length 2379.3
  Top Layer w12: v1(962,1462) 1003.78,1462 1027.84,1486.06 U1.42@1027.84,1514.34 ; v1(2799.29,1175.43) 2877.02,1097.7 2893.31,1097.7 R170.1@2906.01,1085
  Bottom Layer w12: v1(962,1462) 962,1497.6 D27.1@927.55,1532.05 960.5,1565 1090,1565 1211,1444 2184,1444 2452.57,1175.43 v1(2799.29,1175.43)
BOT_REG1: C35.1 C50.1 D14.2 D16.1 pad.1@1183,1192 pad.1@1243,1474 Q31.1 Q33.2 U1.35 | length 1045.4
  Top Layer w12: v1(1123,1454) 1140.42,1436.58 U1.35@1184.34,1436.58 1214.58,1436.58 1243,1465 pad.1@1243,1474
  Bottom Layer w12: v1(1123,1454) 1123,1443.5 C35.1@1148,1418.5 1159.5,1407 1219.69,1407 D14.2@1224.69,1402 1260,1366.69 1260,1335.17 1293.17,1302 1317.96,1302 1340,1279.96 1340,1231.84 Q31.1@1303.76,1195.6 ; pad.1@1183,1192 1196.5,1178.5 1276.38,1178.5 1293.48,1195.6 Q31.1@1303.76,1195.6 ; D16.1@1221.19,1002.31 1239.81,1002.31 C50.1@1268,1030.5 1286.91,1011.59 Q33.2@1313.6,1011.59 1331.99,1011.59 1362,1041.6 1362,1065 1342.06,1084.94 1342.06,1157.3 Q31.1@1303.76,1195.6
BOT_REG2: C34.1 D13.2 R118.2 U1.34 | length 569.5
  Top Layer w12: v1(1020,1414) 1023,1417 U1.34@1184.24,1417
  Bottom Layer w10: C34.1@993,1415.5 993,1414 993,1411 1017,1387 1175.69,1387 D13.2@1224.69,1338
  Bottom Layer w20: R118.2@867,1417 870,1414 C34.1@993,1414 ; C34.1@993,1415.5 994.5,1414 C34.1@996.7,1414
  Bottom Layer w30: C34.1@993,1418.5 993,1417.7 C34.1@996.7,1414
BOT_SHUT: C39.1 pad.1@888,1011 R110.2 R183.1 U1.33 | length 1115.7
  Top Layer w10: v1(953,1233) 956,1233 1120.21,1397.21 U1.33@1184.34,1397.21
  Bottom Layer w10: R183.1@653.5,599.47 671.47,599.47 738,666 738,801.81 739.25,803.06 739.25,807.81 874,942.56 874,1143.9 R110.2@908.6,1178.5 C39.1@968.27,1178.5 969,1179.23 953,1195.23 v1(953,1233)
BOT_WAKE: R87.1 U5.36 | length 201
  Top Layer w10: U5.36@717.14,518.44 898.95,518.44 R87.1@912.5,532
BOTAFE_DCHG: Q25.1 U1.31 | length 487.8
  Top Layer w12: U1.31@1184.34,1357.84 1227.97,1357.84 1331.82,1254 1363.5,1254 1383.11,1234.38 1383.11,1104.11 v1(1333,1054)
  Bottom Layer w12: Q25.1@1303.76,1072.1 1314.9,1072.1 v1(1333,1054)
BOTAFE_DDSG: D49.2 pad.1@1077,924.98 R128.1 U1.32 | length 1669.4
  Top Layer w10: v1(1052,392) 1082,392 D49.2@1084,390
  Top Layer w12: v1(1106,1297) 1106,1330.73 1152.8,1377.53 U1.32@1184.34,1377.53
  Bottom Layer w10: v1(1052,392) 849,392 775,466 775,792.56 894.44,912 1037.63,912 1084,958.37 1084,1155.15 1157,1228.15 1157,1275.5
  Bottom Layer w12: v1(1106,1297) 1127.5,1275.5 1157,1275.5 R128.1@1243,1275.5
CAN_RXD: R193.2 U5.16 | length 183.1
  Top Layer w10: U5.16@484.86,262.54 519.72,262.54 573,209.25 v1(573,186)
  Bottom Layer w10: v1(573,186) 591.5,186 R193.2@613.5,164
CAN_STB: R194.2 U5.14 | length 135.6
  Top Layer w10: U5.14@484.86,301.91 563.09,301.91 v1(573,292)
  Bottom Layer w10: v1(573,292) 580,285 R194.2@613.5,285
CAN_TXD: R197.2 U5.15 | length 152.6
  Top Layer w10: U5.15@484.86,282.22 540.01,282.22 582.23,240 v1(583,240)
  Bottom Layer w10: v1(583,240) 598.5,224.5 R197.2@613.5,224.5
CANH: L2.1 P5.2 | length 75.3
  Bottom Layer w12: P5.2@2256,62 P5.2@2262.5,68.5 ; P5.2@2268,63 2279.17,74.17 L2.1@2279.17,124.5
CANL: L1.1 P5.1 | length 76.1
  Bottom Layer w12: L1.1@2132.76,124.5 2132.76,98.24 P5.1@2168,63
Cell0: P3.1 Q1.2 R21.1 | length 571.1
  Top Layer w20: P3.1@105,829 105,755 135,725 414.16,725 Q1.2@429.76,740.6 580.91,740.6 R21.1@582.5,739
Cell1: P3.2 Q2.2 R1.1 R2.1 R23.1 | length 682.9
  Top Layer w20: R2.1@247.91,777.71 312.2,842 405.69,842 425.07,861.38 Q2.2@429.76,861.38 429.82,861.32 R23.1@582.5,861.3
  Top Layer w40: P3.2@105,927.43 163,869.43 163,835
  Bottom Layer w40: P3.2@105,927.43 197.49,834.93 244,834.93 ; R1.1@247.91,777.71 R1.1@247.91,797.59
  other v1: 220.84,764.04 220.84,792.04
Cell2: P3.3 Q3.2 R3.1 R4.1 R25.1 | length 673.4
  Top Layer w20: R4.1@247.91,898.47 314.44,965 412.6,965 Q3.2@429.76,982.15 581.03,982.15 R25.1@582.5,983.6
  Top Layer w40: P3.3@105,1025.85 105,1009 159,955 211,955
  Bottom Layer w40: P3.3@105,1025.85 175.85,955 234,955
  other v1: 220.84,884.8 220.84,912.8
Cell3: P3.4 Q4.2 R5.1 R6.1 R27.1 | length 666.7
  Top Layer w20: R6.1@247.91,1019.23 315.68,1087 413.82,1087 Q4.2@429.76,1102.93 579.49,1102.93 R27.1@582.5,1105.9
  Top Layer w40: P3.4@105,1124.28 105,1110 139,1076 197,1076 ; 210.05,1019.23 R6.1@247.91,1019.23
  Bottom Layer w40: P3.4@105,1124.28 153.28,1076 223,1076
  other v1: 220.84,1005.56 220.84,1033.56
Cell4: P3.5 Q5.2 R7.1 R8.1 R29.1 | length 690
  Top Layer w20: R8.1@247.91,1139.99 315.93,1208 414.05,1208 Q5.2@429.76,1223.71 577.95,1223.71 R29.1@582.5,1228.26
  Top Layer w40: P3.5@105,1222.7 130.7,1197 190.9,1197 R8.1@247.91,1139.99
  Bottom Layer w40: P3.5@105,1222.7 130.7,1197 236,1197
  other v1: 220.84,1126.32 220.84,1154.32
Cell5: P3.6 Q6.2 R9.1 R10.1 R31.1 | length 608.8
  Top Layer w20: R10.1@247.91,1260.75 314.17,1327 412.27,1327 Q6.2@429.76,1344.49 576.41,1344.49 R31.1@582.5,1350.58
  Top Layer w40: P3.6@105,1321.13 109.13,1317 185,1317
  Bottom Layer w40: P3.6@105,1321.13 108.13,1318 259,1318
  other v1: 220.84,1247.08 220.84,1275.08
Cell6: P3.7 Q7.2 R11.1 R12.1 R33.1 | length 689.8
  Top Layer w20: R12.1@247.91,1381.51 315.41,1449 413.49,1449 Q7.2@429.76,1465.26 574.88,1465.26 R33.1@582.5,1472.89
  Top Layer w40: P3.7@105,1419.55 209.87,1419.55 R12.1@247.91,1381.51
  Bottom Layer w40: P3.7@105,1419.55 209.87,1419.55 R11.1@247.91,1381.51
  other v1: 220.84,1367.84 220.84,1395.84
Cell7: P3.8 Q8.2 R13.1 R14.1 R35.1 | length 671.9
  Top Layer w20: R14.1@247.91,1502.26 315.65,1570 413.71,1570 Q8.2@429.76,1586.04 573.34,1586.04 R35.1@582.5,1595.21
  Top Layer w40: P3.8@105,1517.98 232.2,1517.98 R14.1@247.91,1502.26
  Bottom Layer w40: P3.8@105,1517.98 232.2,1517.98 R13.1@247.91,1502.26
  other v1: 220.84,1488.6 220.84,1516.6
Cell8: P3.9 Q9.2 R15.1 R16.1 R37.1 | length 665
  Top Layer w20: R16.1@241.29,1616.4 R16.1@247.91,1623.02 314.89,1690 412.94,1690 Q9.2@429.76,1706.82 571.8,1706.82 R37.1@582.5,1717.52
  Top Layer w40: P3.9@105,1616.4 R16.1@241.29,1616.4
  Bottom Layer w40: P3.9@105,1616.4 241.29,1616.4 R15.1@247.91,1623.02
  other v1: 220.84,1609.35 220.84,1637.35
Cell9: P3.10 Q10.2 R17.1 R18.1 R39.1 | length 684.2
  Top Layer w20: R18.1@247.91,1743.78 315.13,1811 413.16,1811 Q10.2@429.76,1827.6 570.26,1827.6 R39.1@582.5,1839.84
  Top Layer w40: P3.10@105,1714.83 117.17,1727 231.13,1727 R18.1@247.91,1743.78
  Bottom Layer w40: P3.10@105,1714.83 133.95,1743.78 R17.1@247.91,1743.78
  other v1: 220.84,1730.11 220.84,1758.11
Cell10: D8.2 D11.2 P3.11 R19.1 R20.1 R41.1 R62.2 | length 2028.8
  Top Layer w20: R20.1@247.91,1864.54 314.37,1931 550.5,1931 R41.1@581.5,1962
  Top Layer w30: P3.11@105,1813.25 105.53,1813.78 D8.2@105.53,1962
  Top Layer w40: P3.11@105,1813.25 139.75,1848 231.37,1848 R20.1@247.91,1864.54
  Bottom Layer w20: P3.11@105,1813.25 91,1827.25 91,1939 149,1997 1140.77,1997 R62.2@1165.84,1971.93
  Bottom Layer w40: P3.11@105,1813.25 139.61,1847.86 ; 156.29,1864.54 139.61,1847.86 ; 168,1847.86 139.61,1847.86
  other v1: 220.84,1850.87 220.84,1878.87
Cell10B: P4.1 Q11.2 R62.1 R63.2 R64.1 | length 772.4
  Top Layer w20: R64.1@1289.27,1433.5 1288.93,1433.83 Q11.2@1288.93,1587.24 1271.33,1604.84 1271.33,1886.33 1294,1909 P4.1@1364.33,1909
  Bottom Layer w35: R62.1@1228.83,1971.93 1230.05,1970.71 R63.2@1230.05,1906.5 1361.83,1906.5 P4.1@1364.33,1909
  Bottom Layer w40: P4.1@1364.33,1909 P4.1@1364.33,1917.5
Cell11: P4.2 Q12.2 R42.1 R43.1 R66.1 | length 724.2
  Top Layer w20: R42.1@1325.49,1767.09 1390.33,1702.25 1390.33,1612.52 1409.71,1593.15 Q12.2@1409.71,1587.24 1409.71,1435.31 R66.1@1411.52,1433.5
  Top Layer w40: 1368,1849 1397.85,1849 1398.85,1850 1403.76,1850 P4.2@1462.76,1909 P4.2@1460.16,1909 ; P4.2@1467.41,1909 P4.2@1467.91,1909
  Bottom Layer w40: R43.1@1325.49,1767.09 1325.49,1828.97 1347.53,1851 1404.76,1851 P4.2@1462.76,1909
  other v1: 1311.82,1794.16 1339.82,1794.16
Cell12: P4.3 Q13.2 R44.1 R45.1 R68.1 | length 720.8
  Top Layer w20: R44.1@1446.25,1767.09 1513.33,1700.01 1513.33,1604.4 Q13.2@1530.49,1587.24 1530.49,1436.78 R68.1@1533.77,1433.5
  Top Layer w40: R44.1@1446.25,1767.09 R44.1@1446.25,1783.25 ; 1503,1807.5 1503,1870.72 1541.28,1909 P4.3@1561.18,1909
  Bottom Layer w40: R45.1@1446.25,1767.09 1446.25,1807.76 1547.5,1909 P4.3@1561.18,1909
  other v1: 1432.58,1794.16 1460.58,1794.16
Cell13: P4.4 Q14.2 R46.1 R47.1 R70.1 | length 750.6
  Top Layer w20: R46.1@1573.63,1773.71 1634.33,1713.01 1634.33,1604.18 Q14.2@1651.26,1587.24 1651.26,1438.26 R70.1@1656.02,1433.5
  Top Layer w40: R46.1@1567.01,1767.09 1573.63,1773.71 1573.63,1836.3 1646.33,1909 P4.4@1659.61,1909
  Bottom Layer w40: R47.1@1567.01,1767.09 1567.01,1830.01 1646,1909 P4.4@1659.61,1909
  other v1: 1553.34,1794.16 1581.34,1794.16
Cell14: P4.5 Q15.2 R48.1 R49.1 R72.1 | length 679.4
  Top Layer w20: R48.1@1687.77,1767.09 1755.33,1699.52 1755.33,1603.95 Q15.2@1772.04,1587.24 1772.04,1439.73 R72.1@1778.28,1433.5
  Top Layer w40: R48.1@1687.77,1767.09 1706,1785.32 1706,1844 ; 1744,1862 1744,1894.97 P4.5@1758.03,1909
  Bottom Layer w40: R49.1@1687.77,1767.09 1687.77,1838.74 P4.5@1758.03,1909
  other v1: 1674.1,1794.16 1702.1,1794.16
Cell15: P4.6 Q16.2 R50.1 R51.1 R74.1 | length 695.2
  Top Layer w20: R50.1@1808.53,1767.09 1875.33,1700.28 1875.33,1604.73 Q16.2@1892.82,1587.24 1892.82,1441.21 R74.1@1900.53,1433.5
  Top Layer w40: R50.1@1808.53,1767.09 1856.46,1815.02 P4.6@1856.46,1909
  Bottom Layer w40: R51.1@1808.53,1767.09 1825,1783.56 1825,1877.54 P4.6@1856.46,1909
  other v1: 1794.86,1794.16 1822.86,1794.16
Cell16: P4.7 Q17.2 R52.1 R53.1 R76.1 | length 677.3
  Top Layer w20: R52.1@1929.29,1767.09 1997.33,1699.04 1997.33,1603.51 Q17.2@2013.6,1587.24 2013.6,1442.68 R76.1@2022.78,1433.5
  Top Layer w35: R52.1@1929.29,1767.09 1954.88,1792.68 P4.7@1954.88,1909
  Bottom Layer w40: R53.1@1929.29,1767.09 1946,1783.8 1946,1900.12 P4.7@1954.88,1909
  other v1: 1915.62,1794.16 1943.62,1794.16
Cell17: P4.8 Q18.2 R54.1 R55.1 R78.1 | length 659.5
  Top Layer w20: R54.1@2050.04,1767.09 2117.33,1699.8 2117.33,1604.29 Q18.2@2134.37,1587.24 2134.37,1444.16 R78.1@2145.03,1433.5
  Top Layer w40: R54.1@2050.04,1767.09 2050.04,1905.74 P4.8@2053.31,1909
  Bottom Layer w40: R55.1@2050.04,1767.09 2050.04,1905.74 P4.8@2053.31,1909
  other v1: 2036.38,1794.16 2064.38,1794.16
Cell18: P4.9 Q19.2 R56.1 R57.1 R80.1 | length 673.2
  Top Layer w20: R56.1@2170.8,1767.09 2238.33,1699.56 2238.33,1604.06 Q19.2@2255.15,1587.24 2255.15,1445.63 R80.1@2267.29,1433.5
  Top Layer w40: P4.9@2151.73,1909 2158,1902.73 2158,1779.89 R56.1@2170.8,1767.09
  Bottom Layer w40: P4.9@2151.73,1909 2151.73,1786.16 R57.1@2170.8,1767.09
  other v1: 2157.13,1794.16 2185.13,1794.16
Cell19: P4.10 Q20.2 R58.1 R59.1 R82.1 | length 692.3
  Top Layer w20: R58.1@2291.56,1767.09 2358.33,1700.32 2358.33,1604.84 Q20.2@2375.93,1587.24 2375.93,1447.11 R82.1@2389.54,1433.5
  Top Layer w40: P4.10@2250.16,1909 2275,1884.16 2275,1783.65 R58.1@2291.56,1767.09
  Bottom Layer w40: P4.10@2250.16,1909 2250.16,1808.49 2285.19,1773.46 R59.1@2291.56,1767.09
  other v1: 2277.89,1794.16 2305.89,1794.16
Cell20: P4.11 R60.1 R61.1 R84.1 R218.2 | length 724.3
  Top Layer w20: R60.1@2412.32,1767.09 2490.33,1689.07 2490.33,1454.43 R84.1@2511.27,1433.5
  Top Layer w38: P4.11@2348.58,1909 2416.11,1976.52 R218.2@2483.84,1976.52
  Top Layer w40: P4.11@2348.58,1909 2363,1909 2396.04,1875.96 2396.04,1783.37 R60.1@2412.32,1767.09
  Bottom Layer w40: P4.11@2348.58,1909 P4.11@2348.58,1918.75
  other v1: 2398.65,1794.16 2426.65,1794.16
CFETOFF: R185.2 U1.29 | length 170.4
  Top Layer w10: R185.2@1281.14,1218.14 R185.2@1289.06,1210.23
  Top Layer w12: U1.29@1184.34,1318.47 1216.43,1318.47 1276,1258.91 1276,1223.29 R185.2@1281.14,1218.14
Current+: C59.2 D33.2 D35.2 pad.1@1047,692 Q47.2 R103.1 R165.1 R217.2 R219.1 R220.1 R221.1 R222.1 | length 2639
  Top Layer w10: R103.1@996.28,859.5 1021,834.79 v1(1021,696)
  Bottom Layer w10: v1(1021,696) 1259,458 2684,458 2704,478 2704,545
  Bottom Layer w20: D33.2@2940.53,593 2940.53,544.47 2987,498 3066.5,498 C59.2@3067,498.5 3076.66,498.5 Q47.2@3127.76,447.4 3176,399.16 3176,338 3148.5,310.5 R165.1@3067,310.5
  Bottom Layer w35: R217.2@2384.5,506 2466.76,506
  other v1: 2553,602 2580,602 2607,602 2634,602 2661,602 2688,602 2715,602 2742,602 2769,602 2796,602 2823,602 2850,602 2553,629 2580,629 2607,629 2634,629 2661,629 2688,629 2715,629 2742,629 2769,629 2796,629 2823,629 2850,629
DET: D38.1 P7.1 | length 75.9
  Bottom Layer w20: P7.1@795,68 806.79,56.21 D38.1@866,56.21
DFETOFF: R181.2 U1.30 | length 220
  Top Layer w10: R181.2@1348.72,1210.23 R181.2@1350,1210.23
  Top Layer w12: U1.30@1184.34,1338.16 1222.2,1338.16 1350,1210.36 R181.2@1350,1210.23
Dri_Test: D28.2 D29.2 pad.1@3171.85,516.04 R157.1 R164.1 R166.1 | length 1068.5
  Bottom Layer w12: R157.1@2695,926 2753.5,926 2765,914.5 2765,914.3 2777.7,901.6 3069.4,901.6 3103,868 3103,561 3185,479 R166.1@3259.5,479 3280,458.5 3280,420.35 D29.2@3290.35,410 3290.35,383.48 D28.2@3312,361.83
GND: C1.2 C11.2 C23.1 C25.1 C27.2 C30.2 C34.2 C35.2 C39.2 C40.2 C42.2 C43.1 C44.2 C46.2 C48.2 C51.2 C54.2 C62.2 C63.1 C64.1 C65.2 C66.2 C67.2 C68.2 C69.2 C70.1 C71.2 C72.2 C73.2 C74.2 C75.2 C79.2 C80.2 C81.2 D2.2 D3.2 D15.2 D26.2 D27.2 D39.2 D40.2 D41.2 D45.2 D47.3 P1.4 P7.2 pad.1@387,188.5 pad.1@503,269 pad.1@766,762 pad.1@804,1616.4 pad.1@1041,1600 pad.1@1481,268 pad.1@2349.57,255 Q21.2 Q22.2 Q26.2 Q29.2 R86.2 R91.2 R94.1 R100.2 R110.1 R114.1 R123.1 R132.1 R189.1 R190.1 R191.1 R210.1 R214.1 R217.1 RT1.1 RT3.1 RT5.1 RT7.1 S1.2 U1.17 U3.4 U4.2 U4.3 U4.5 U4.7@1945,365 U5.11 U6.2 U7.5 U8.3 U9.1 U9.9@2779.33,1528 | length 261
  Top Layer w12: C64.1@399,309.52 450.44,360.96 U5.11@484.86,360.96 ; C11.2@930,1052 930,1054.88 C1.2@973.62,1098.5 988.47,1113.35 U1.17@988.47,1181.66
  other v1: 1249,83 1276,83 1813,88 1813,115 2329,180 368,270 396,270 424,270 597,375 1353,396 1380,396 1407,396 597,403 597,431 1599,498 2310,532 398,533 2310,559 398,561 621,694 649,694 1175,835 1203,835 1172,961 951,965.87 1174,993 951,993.87 954,1066 912.47,1355.5 940.47,1355.5 978,1690 978,1718
  other v2: 1923.35,365 1966.65,365 2757.68,1502.41 2800.99,1502.41 2757.68,1553.59 2800.99,1553.59
  other v3: 2757.68,1451.23 2800.99,1451.23 2757.68,1604.77 2800.99,1604.77
LED1: D42.2 U5.19 | length 88
  Top Layer w10: D42.2@468,122.5 484.86,139.35 U5.19@484.86,203.48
